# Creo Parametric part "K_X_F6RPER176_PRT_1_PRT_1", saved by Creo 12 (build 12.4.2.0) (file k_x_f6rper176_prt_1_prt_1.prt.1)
Units: Custom; MM, KILOGRAM, SECS

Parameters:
  PTC_WM_ITERATION = "0"
  PTC_WM_VERSION = "-.0"
  PTC_WM_LIFECYCLE_STATE = "In Work"
  PTC_WM_LIFECYCLE = "MO_CADDocument"
  PTC_WM_CREATED_BY = "Maximilian Roepper (Z0017RMS: MO)"
  PTC_WM_CREATED_ON = "18-Sep-26 11:36:42 AM"
  PTC_WM_MODIFIED_BY = "Maximilian Roepper (Z0017RMS: MO)"
  PTC_WM_MODIFIED_ON = "18-Sep-26 11:36:46 AM"
  PDMLINKNUMBER = "PDM000071455144"
  PTC_WM_NAME = "k_x_f6rper176_prt_1_prt_1.prt"
  PTC_WM_NUMBER = "PDM000071455144"

Other parameters: WEIGHT, WEIGHT_FACTOR, WEIGHT_ADD, _MASS_TEMP, _DIFF_TEMP, MC_ERRORS, SUPPLIER

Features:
  1. coordinate system
  2. datum plane "PRT_YZ"
  3. datum plane "PRT_XY"
  4. datum plane "PRT_XZ"
  5. coordinate system
  6. datum axis
  7. datum axis
  8. datum axis
  9. coordinate system
  10. imported feature
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
Other named items: PRT, SIEMENS_MO, DRW_VIEW_ORG, PRT_X, PRT_Y, PRT_Z, CS0, ROUGH_GROB

Layers: 00_STD_CSYS-KSYS, 01_STD_PLANES-EBENEN, 02_STD_AXES-ACHSEN, 03_STD_CSYS-KSYS, 24_IMPORT_FEAT-IMPORT_KE

Surfaces: 7 plane, 4 tabulated cylinder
